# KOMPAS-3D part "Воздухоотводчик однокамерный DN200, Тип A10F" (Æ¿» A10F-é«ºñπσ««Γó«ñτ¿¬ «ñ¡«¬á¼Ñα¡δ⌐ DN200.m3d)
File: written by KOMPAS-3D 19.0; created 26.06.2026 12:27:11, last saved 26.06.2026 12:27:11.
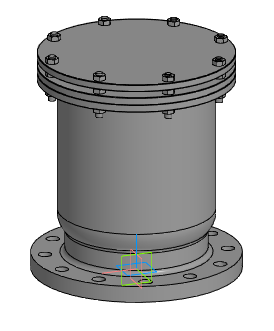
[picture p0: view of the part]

Document properties: Автор: Энергия; Полное имя файла: Z:\3.Личные\kachalov\001_3d для проектировщиков\х.х Тип A10F Воздухоотводчик однокамерный фланцевый\_step\Тип A10F-Воздухоотводчик однокамерный DN200.m3d

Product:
- Part/product: Воздухоотводчик однокамерный DN200  | designation Тип A10F

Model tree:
1. Операция без истории:1  (labels: Тип A10F; Воздухоотводчик однокамерный DN200)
